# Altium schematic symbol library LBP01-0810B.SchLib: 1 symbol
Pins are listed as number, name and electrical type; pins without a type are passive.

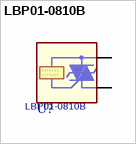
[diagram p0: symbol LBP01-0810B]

## LBP01-0810B
designator U?
footprint ST_SMBB
pins: 1, 2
